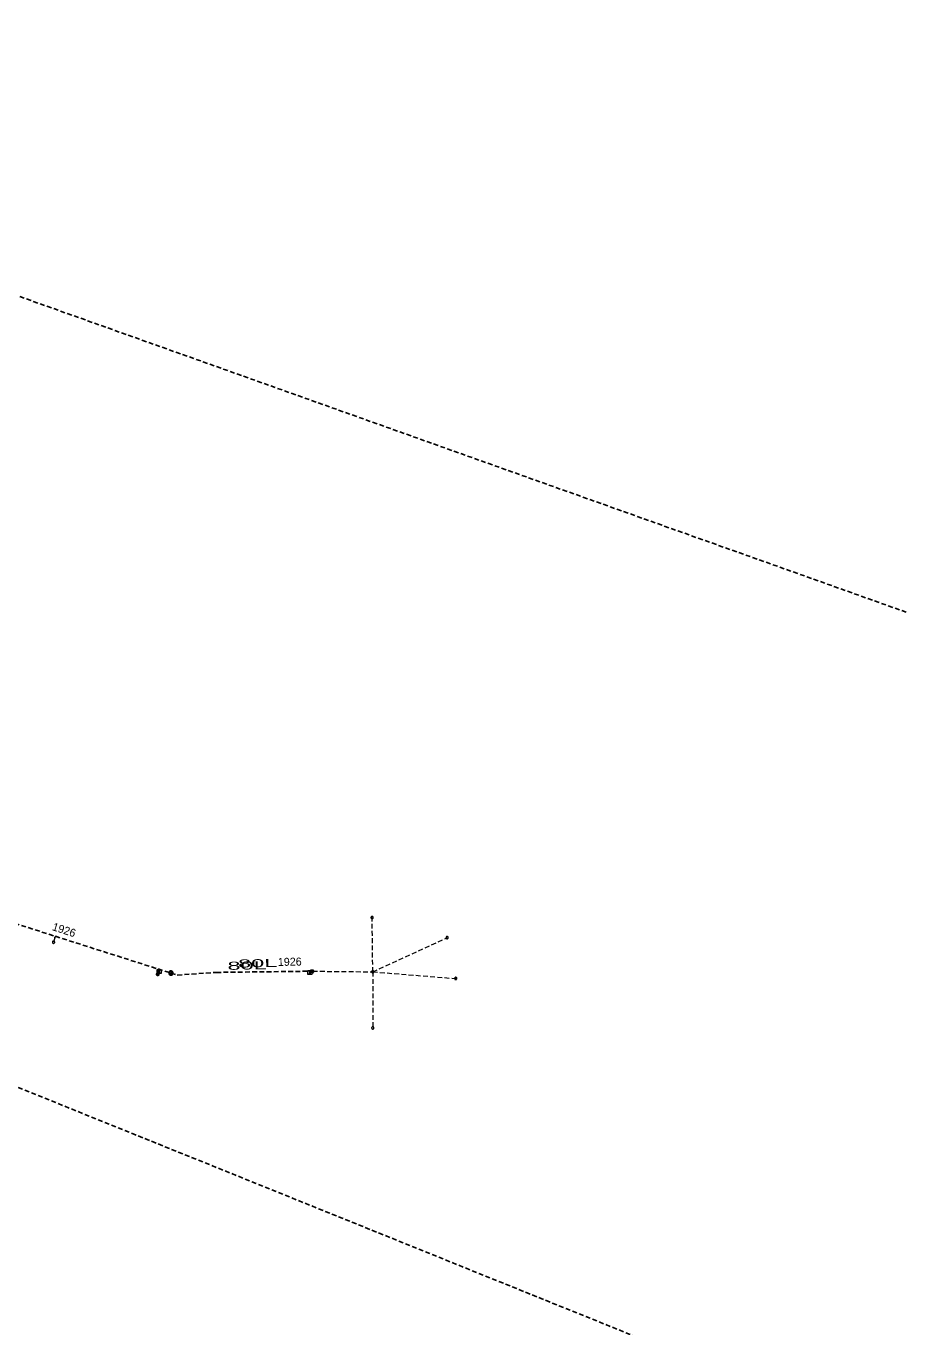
# Model space of a CAD drawing. Extents: x -739741 to -739027, y -1046215 to -1045797.
# Drawn here: x -739558.3 to -739383.7, y -1046072.8 to -1045812.7 of the extents above; entities that cross this region are included whole.
import ezdxf

# ---------------------------------------------------------------- set-up
doc = ezdxf.new("R2010")
doc.units = 0
doc.header["$LTSCALE"] = 0.32
doc.linetypes.add('MEDIUM_DASHED', pattern=[4.5, 3, -1.5])
doc.layers.add('15', color=7, linetype='Continuous')
doc.layers.add('63', color=7, linetype='MEDIUM_DASHED', lineweight=25)
doc.layers.add('8', color=7, linetype='Continuous', lineweight=13)

msp = doc.modelspace()

# ---------------------------------------------------------------- linework, layer by layer
at = {"layer": '63'}
msp.add_lwpolyline([(-739088.915, -1046214.93), (-739738.392, -1045952.844), (-739738.394, -1045952.843), (-739738.395, -1045952.842), (-739738.397, -1045952.841), (-739738.398, -1045952.839), (-739738.398, -1045952.837), (-739738.398, -1045952.835), (-739738.398, -1045952.833), (-739734.244, -1045922.471), (-739734.244, -1045922.47), (-739711.46, -1045812.716), (-739711.459, -1045812.714), (-739711.458, -1045812.713), (-739711.457, -1045812.711), (-739711.456, -1045812.71), (-739711.454, -1045812.709), (-739711.452, -1045812.709), (-739711.45, -1045812.708), (-739711.448, -1045812.708), (-739711.447, -1045812.709), (-739026.908, -1046056.391)], dxfattribs=at)
at = {"layer": '8', "linetype": 'MEDIUM_DASHED'}
for p, q in [((-739552.473, -1045994.974), (-739552.745, -1045995.855)), ((-739552.384, -1045994.685), (-739552.473, -1045994.974)), ((-739488.929, -1046001.785), (-739474.05, -1045994.955)), ((-739531.866, -1046001.222), (-739531.912, -1046001.633)), ((-739531.912, -1046001.633), (-739531.984, -1046002.256)), ((-739488.929, -1046001.785), (-739472.342, -1046003.126)), ((-739488.929, -1046001.785), (-739488.929, -1046013.004))]:
    msp.add_line(p, q, dxfattribs=at)
at = {"layer": '8'}
for p, q in [((-739552.333, -1045995.016), (-739552.624, -1045994.927)), ((-739531.767, -1046001.649), (-739532.069, -1046001.614))]:
    msp.add_line(p, q, dxfattribs=at)
at = {"layer": '8', "linetype": 'MEDIUM_DASHED', "lineweight": 25}
for points in [[(-739597.028, -1045984.409), (-739571.526, -1045988.586), (-739552.384, -1045994.685), (-739531.866, -1046001.222), (-739529.274, -1046002.048)], [(-739529.274, -1046002.048), (-739528.017, -1046002.449), (-739520.23, -1046001.904), (-739501.196, -1046001.663)]]:
    msp.add_lwpolyline(points, dxfattribs=at)
at = {"layer": '8', "linetype": 'MEDIUM_DASHED'}
msp.add_lwpolyline([(-739501.196, -1046001.663), (-739500.936, -1046001.665), (-739488.929, -1046001.785), (-739489.05, -1045990.931)], dxfattribs=at)
at = {"layer": '8'}
for points in [[(-739489.063, -1045990.7), (-739489.115, -1045990.706), (-739489.164, -1045990.725), (-739489.208, -1045990.753), (-739489.245, -1045990.792), (-739489.271, -1045990.837), (-739489.287, -1045990.887), (-739489.291, -1045990.939), (-739489.283, -1045990.991), (-739489.264, -1045991.04), (-739489.233, -1045991.084), (-739489.194, -1045991.118), (-739489.149, -1045991.144), (-739489.097, -1045991.158), (-739489.045, -1045991.16), (-739488.994, -1045991.152), (-739488.946, -1045991.13), (-739488.903, -1045991.1), (-739488.869, -1045991.059), (-739488.845, -1045991.013), (-739488.832, -1045990.962), (-739488.83, -1045990.91), (-739488.841, -1045990.858), (-739488.863, -1045990.81), (-739488.896, -1045990.769), (-739488.936, -1045990.736), (-739488.983, -1045990.713), (-739489.035, -1045990.701)], [(-739552.968, -1045995.796), (-739552.978, -1045995.848), (-739552.975, -1045995.901), (-739552.962, -1045995.951), (-739552.936, -1045995.998), (-739552.901, -1045996.037), (-739552.858, -1045996.067), (-739552.81, -1045996.087), (-739552.758, -1045996.096), (-739552.706, -1045996.092), (-739552.655, -1045996.076), (-739552.61, -1045996.049), (-739552.572, -1045996.014), (-739552.543, -1045995.97), (-739552.524, -1045995.921), (-739552.517, -1045995.869), (-739552.523, -1045995.817), (-739552.538, -1045995.767), (-739552.566, -1045995.722), (-739552.603, -1045995.685), (-739552.648, -1045995.657), (-739552.697, -1045995.639), (-739552.75, -1045995.634), (-739552.802, -1045995.641), (-739552.852, -1045995.659), (-739552.895, -1045995.687), (-739552.932, -1045995.725), (-739552.958, -1045995.77)], [(-739473.844, -1045994.849), (-739473.871, -1045994.804), (-739473.908, -1045994.766), (-739473.952, -1045994.738), (-739474.002, -1045994.72), (-739474.054, -1045994.714), (-739474.106, -1045994.72), (-739474.156, -1045994.738), (-739474.2, -1045994.766), (-739474.237, -1045994.803), (-739474.264, -1045994.849), (-739474.28, -1045994.899), (-739474.285, -1045994.951), (-739474.277, -1045995.003), (-739474.258, -1045995.052), (-739474.229, -1045995.096), (-739474.19, -1045995.131), (-739474.145, -1045995.157), (-739474.094, -1045995.172), (-739474.042, -1045995.175), (-739473.99, -1045995.166), (-739473.942, -1045995.146), (-739473.898, -1045995.116), (-739473.864, -1045995.076), (-739473.839, -1045995.029), (-739473.826, -1045994.979), (-739473.824, -1045994.926), (-739473.834, -1045994.875)], [(-739532.056, -1046001.314), (-739531.267, -1046001.314), (-739531.267, -1046002.114), (-739532.056, -1046002.114)], [(-739500.965, -1046001.652), (-739500.971, -1046001.6), (-739500.989, -1046001.55), (-739501.017, -1046001.506), (-739501.055, -1046001.469), (-739501.1, -1046001.442), (-739501.15, -1046001.426), (-739501.202, -1046001.421), (-739501.254, -1046001.428), (-739501.303, -1046001.447), (-739501.347, -1046001.477), (-739501.382, -1046001.516), (-739501.408, -1046001.561), (-739501.423, -1046001.612), (-739501.426, -1046001.664), (-739501.418, -1046001.716), (-739501.397, -1046001.764), (-739501.367, -1046001.807), (-739501.327, -1046001.842), (-739501.281, -1046001.866), (-739501.23, -1046001.88), (-739501.178, -1046001.882), (-739501.126, -1046001.872), (-739501.078, -1046001.85), (-739501.036, -1046001.818), (-739501.003, -1046001.778), (-739500.979, -1046001.731), (-739500.967, -1046001.68)], [(-739500.704, -1046001.673), (-739500.706, -1046001.62), (-739500.72, -1046001.569), (-739500.744, -1046001.523), (-739500.779, -1046001.483), (-739500.822, -1046001.452), (-739500.871, -1046001.432), (-739500.922, -1046001.423), (-739500.974, -1046001.426), (-739501.025, -1046001.441), (-739501.071, -1046001.467), (-739501.109, -1046001.503), (-739501.139, -1046001.546), (-739501.158, -1046001.596), (-739501.165, -1046001.647), (-739501.161, -1046001.7), (-739501.144, -1046001.749), (-739501.118, -1046001.795), (-739501.081, -1046001.833), (-739501.037, -1046001.86), (-739500.987, -1046001.879), (-739500.935, -1046001.885), (-739500.883, -1046001.879), (-739500.833, -1046001.861), (-739500.789, -1046001.832), (-739500.752, -1046001.795), (-739500.725, -1046001.75), (-739500.709, -1046001.7)], [(-739532.215, -1046002.239), (-739532.215, -1046002.292), (-739532.203, -1046002.343), (-739532.18, -1046002.39), (-739532.147, -1046002.432), (-739532.105, -1046002.464), (-739532.057, -1046002.485), (-739532.006, -1046002.496), (-739531.954, -1046002.495), (-739531.903, -1046002.482), (-739531.856, -1046002.457), (-739531.817, -1046002.422), (-739531.786, -1046002.381), (-739531.765, -1046002.332), (-739531.756, -1046002.28), (-739531.758, -1046002.228), (-739531.773, -1046002.178), (-739531.798, -1046002.132), (-739531.834, -1046002.092), (-739531.877, -1046002.063), (-739531.926, -1046002.043), (-739531.977, -1046002.035), (-739532.03, -1046002.039), (-739532.08, -1046002.056), (-739532.126, -1046002.083), (-739532.163, -1046002.119), (-739532.192, -1046002.163), (-739532.21, -1046002.212)], [(-739531.606, -1046002.265), (-739531.612, -1046002.213), (-739531.63, -1046002.163), (-739531.658, -1046002.119), (-739531.696, -1046002.082), (-739531.741, -1046002.055), (-739531.791, -1046002.039), (-739531.843, -1046002.034), (-739531.895, -1046002.041), (-739531.944, -1046002.06), (-739531.988, -1046002.09), (-739532.023, -1046002.129), (-739532.049, -1046002.174), (-739532.064, -1046002.225), (-739532.067, -1046002.277), (-739532.059, -1046002.329), (-739532.038, -1046002.377), (-739532.008, -1046002.42), (-739531.968, -1046002.455), (-739531.922, -1046002.479), (-739531.871, -1046002.493), (-739531.819, -1046002.495), (-739531.767, -1046002.485), (-739531.719, -1046002.463), (-739531.677, -1046002.431), (-739531.644, -1046002.391), (-739531.62, -1046002.344), (-739531.608, -1046002.293)], [(-739528.956, -1046002.045), (-739528.963, -1046001.984), (-739528.981, -1046001.924), (-739529.01, -1046001.869), (-739529.049, -1046001.821), (-739529.096, -1046001.781), (-739529.15, -1046001.751), (-739529.209, -1046001.731), (-739529.271, -1046001.724), (-739529.333, -1046001.728), (-739529.392, -1046001.744), (-739529.448, -1046001.772), (-739529.498, -1046001.809), (-739529.539, -1046001.856), (-739529.571, -1046001.909), (-739529.591, -1046001.968), (-739529.601, -1046002.029), (-739529.598, -1046002.091), (-739529.583, -1046002.151), (-739529.557, -1046002.208), (-739529.521, -1046002.258), (-739529.475, -1046002.301), (-739529.423, -1046002.333), (-739529.365, -1046002.356), (-739529.304, -1046002.366), (-739529.242, -1046002.365), (-739529.181, -1046002.352), (-739529.124, -1046002.327), (-739529.073, -1046002.292), (-739529.029, -1046002.248), (-739528.995, -1046002.196), (-739528.971, -1046002.139), (-739528.959, -1046002.078)], [(-739529.071, -1046002.045), (-739529.076, -1046001.996), (-739529.093, -1046001.949), (-739529.122, -1046001.908), (-739529.16, -1046001.875), (-739529.204, -1046001.851), (-739529.252, -1046001.839), (-739529.302, -1046001.838), (-739529.35, -1046001.85), (-739529.395, -1046001.872), (-739529.433, -1046001.905), (-739529.462, -1046001.945), (-739529.481, -1046001.992), (-739529.488, -1046002.041), (-739529.483, -1046002.091), (-739529.466, -1046002.138), (-739529.439, -1046002.18), (-739529.402, -1046002.214), (-739529.358, -1046002.238), (-739529.311, -1046002.252), (-739529.261, -1046002.253), (-739529.212, -1046002.243), (-739529.167, -1046002.221), (-739529.128, -1046002.189), (-739529.098, -1046002.15), (-739529.079, -1046002.104), (-739529.071, -1046002.054)], [(-739501.897, -1046001.493), (-739501.108, -1046001.493), (-739501.108, -1046002.293), (-739501.897, -1046002.293)], [(-739500.708, -1046001.737), (-739500.715, -1046001.685), (-739500.732, -1046001.635), (-739500.761, -1046001.591), (-739500.799, -1046001.554), (-739500.843, -1046001.527), (-739500.894, -1046001.511), (-739500.946, -1046001.506), (-739500.997, -1046001.513), (-739501.046, -1046001.532), (-739501.09, -1046001.562), (-739501.125, -1046001.601), (-739501.152, -1046001.646), (-739501.166, -1046001.697), (-739501.169, -1046001.749), (-739501.161, -1046001.801), (-739501.141, -1046001.849), (-739501.11, -1046001.892), (-739501.071, -1046001.927), (-739501.024, -1046001.951), (-739500.973, -1046001.965), (-739500.921, -1046001.967), (-739500.87, -1046001.957), (-739500.821, -1046001.935), (-739500.779, -1046001.903), (-739500.747, -1046001.863), (-739500.723, -1046001.816), (-739500.71, -1046001.765)], [(-739488.698, -1046001.774), (-739488.704, -1046001.722), (-739488.722, -1046001.672), (-739488.75, -1046001.628), (-739488.788, -1046001.591), (-739488.833, -1046001.564), (-739488.883, -1046001.548), (-739488.935, -1046001.543), (-739488.987, -1046001.55), (-739489.036, -1046001.569), (-739489.08, -1046001.599), (-739489.115, -1046001.638), (-739489.141, -1046001.683), (-739489.156, -1046001.734), (-739489.159, -1046001.786), (-739489.151, -1046001.838), (-739489.13, -1046001.886), (-739489.1, -1046001.929), (-739489.06, -1046001.964), (-739489.014, -1046001.988), (-739488.963, -1046002.002), (-739488.911, -1046002.004), (-739488.859, -1046001.994), (-739488.811, -1046001.972), (-739488.769, -1046001.94), (-739488.736, -1046001.9), (-739488.712, -1046001.853), (-739488.7, -1046001.802)], [(-739472.11, -1046003.134), (-739472.112, -1046003.081), (-739472.126, -1046003.03), (-739472.15, -1046002.984), (-739472.185, -1046002.944), (-739472.228, -1046002.913), (-739472.277, -1046002.893), (-739472.328, -1046002.884), (-739472.38, -1046002.887), (-739472.431, -1046002.902), (-739472.477, -1046002.928), (-739472.515, -1046002.964), (-739472.545, -1046003.007), (-739472.564, -1046003.057), (-739472.571, -1046003.108), (-739472.567, -1046003.161), (-739472.55, -1046003.21), (-739472.524, -1046003.256), (-739472.487, -1046003.294), (-739472.443, -1046003.321), (-739472.393, -1046003.34), (-739472.341, -1046003.346), (-739472.289, -1046003.34), (-739472.239, -1046003.322), (-739472.195, -1046003.293), (-739472.158, -1046003.256), (-739472.131, -1046003.211), (-739472.115, -1046003.161)], [(-739488.918, -1046013.235), (-739488.866, -1046013.229), (-739488.816, -1046013.211), (-739488.772, -1046013.183), (-739488.735, -1046013.145), (-739488.708, -1046013.1), (-739488.692, -1046013.05), (-739488.687, -1046012.998), (-739488.694, -1046012.946), (-739488.713, -1046012.897), (-739488.743, -1046012.853), (-739488.782, -1046012.818), (-739488.827, -1046012.792), (-739488.878, -1046012.777), (-739488.93, -1046012.773), (-739488.982, -1046012.781), (-739489.03, -1046012.802), (-739489.073, -1046012.832), (-739489.108, -1046012.872), (-739489.132, -1046012.918), (-739489.146, -1046012.969), (-739489.148, -1046013.021), (-739489.138, -1046013.073), (-739489.116, -1046013.121), (-739489.084, -1046013.163), (-739489.044, -1046013.196), (-739488.997, -1046013.22), (-739488.946, -1046013.232)]]:
    msp.add_lwpolyline(points, close=True, dxfattribs=at)
for points in [[(-739531.507, -1046001.56), (-739531.512, -1046001.517), (-739531.529, -1046001.476), (-739531.556, -1046001.442), (-739531.593, -1046001.416), (-739531.634, -1046001.401), (-739531.677, -1046001.398), (-739531.72, -1046001.406), (-739531.759, -1046001.426), (-739531.792, -1046001.455), (-739531.815, -1046001.493), (-739531.826, -1046001.535), (-739531.828, -1046001.578), (-739531.816, -1046001.621), (-739531.794, -1046001.658), (-739531.762, -1046001.689), (-739531.723, -1046001.709), (-739531.681, -1046001.718), (-739531.654, -1046001.718)], [(-739531.83, -1046001.897), (-739531.82, -1046001.94), (-739531.798, -1046001.979), (-739531.767, -1046002.01), (-739531.728, -1046002.031), (-739531.686, -1046002.042), (-739531.642, -1046002.04), (-739531.6, -1046002.027), (-739531.563, -1046002.003), (-739531.534, -1046001.97), (-739531.515, -1046001.93), (-739531.507, -1046001.887), (-739531.511, -1046001.843), (-739531.527, -1046001.802), (-739531.553, -1046001.767), (-739531.588, -1046001.74), (-739531.629, -1046001.723), (-739531.654, -1046001.718)], [(-739528.843, -1046002.037), (-739528.846, -1046001.992), (-739528.853, -1046001.947), (-739528.865, -1046001.902), (-739528.88, -1046001.86), (-739528.902, -1046001.819), (-739528.927, -1046001.78), (-739528.956, -1046001.745), (-739528.988, -1046001.712), (-739529.024, -1046001.684), (-739529.061, -1046001.659), (-739529.103, -1046001.638), (-739529.146, -1046001.621), (-739529.19, -1046001.609), (-739529.235, -1046001.602), (-739529.281, -1046001.6), (-739529.326, -1046001.602), (-739529.372, -1046001.609), (-739529.416, -1046001.621), (-739529.459, -1046001.638), (-739529.5, -1046001.659), (-739529.538, -1046001.684), (-739529.574, -1046001.712), (-739529.606, -1046001.745), (-739529.635, -1046001.78), (-739529.66, -1046001.819), (-739529.681, -1046001.86), (-739529.696, -1046001.902), (-739529.709, -1046001.947), (-739529.716, -1046001.992), (-739529.718, -1046002.038), (-739529.716, -1046002.083), (-739529.709, -1046002.128), (-739529.696, -1046002.173), (-739529.681, -1046002.215), (-739529.66, -1046002.256), (-739529.635, -1046002.295), (-739529.606, -1046002.33), (-739529.574, -1046002.363), (-739529.538, -1046002.391), (-739529.5, -1046002.416), (-739529.459, -1046002.437), (-739529.416, -1046002.454), (-739529.372, -1046002.465), (-739529.326, -1046002.473), (-739529.281, -1046002.475), (-739529.235, -1046002.473), (-739529.19, -1046002.465), (-739529.146, -1046002.454), (-739529.103, -1046002.437), (-739529.061, -1046002.416), (-739529.024, -1046002.391), (-739528.988, -1046002.363), (-739528.956, -1046002.33), (-739528.927, -1046002.295), (-739528.902, -1046002.256), (-739528.88, -1046002.215), (-739528.865, -1046002.173), (-739528.853, -1046002.128), (-739528.846, -1046002.083), (-739528.843, -1046002.038)], [(-739501.671, -1046002.076), (-739501.661, -1046002.119), (-739501.639, -1046002.158), (-739501.608, -1046002.189), (-739501.57, -1046002.21), (-739501.527, -1046002.221), (-739501.483, -1046002.219), (-739501.441, -1046002.206), (-739501.404, -1046002.182), (-739501.375, -1046002.149), (-739501.356, -1046002.109), (-739501.348, -1046002.066), (-739501.352, -1046002.022), (-739501.368, -1046001.981), (-739501.394, -1046001.946), (-739501.429, -1046001.919), (-739501.47, -1046001.902), (-739501.495, -1046001.897)], [(-739501.348, -1046001.739), (-739501.353, -1046001.696), (-739501.37, -1046001.655), (-739501.397, -1046001.621), (-739501.434, -1046001.595), (-739501.475, -1046001.58), (-739501.518, -1046001.577), (-739501.561, -1046001.585), (-739501.6, -1046001.605), (-739501.633, -1046001.634), (-739501.656, -1046001.672), (-739501.668, -1046001.714), (-739501.669, -1046001.757), (-739501.657, -1046001.8), (-739501.635, -1046001.837), (-739501.603, -1046001.868), (-739501.565, -1046001.888), (-739501.522, -1046001.897), (-739501.495, -1046001.897)]]:
    msp.add_lwpolyline(points, dxfattribs=at)

# ---------------------------------------------------------------- texts
at = {"layer": '15'}
for rotation, p in [(342, (-739553.155, -1045993.424)), (1, (-739507.89, -1046000.614))]:
    msp.add_text('1926', height=1.6, rotation=rotation, dxfattribs=at).set_placement(p)
at = {"layer": '15', "width": 2.2}
for p in [(-739517.967, -1046001.396), (-739515.845, -1046000.936)]:
    msp.add_text('80L ', height=1.6, rotation=1, dxfattribs=at).set_placement(p)

doc.saveas('drawing.dxf')
